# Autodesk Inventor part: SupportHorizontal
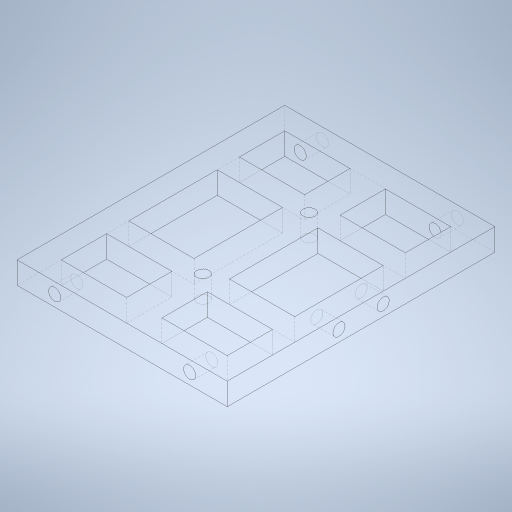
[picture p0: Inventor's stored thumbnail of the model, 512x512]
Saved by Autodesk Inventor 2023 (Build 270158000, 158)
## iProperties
Created: 2023-10
Part Number: SupportHorizontal
Material: Aluminum 7075
Document SubType Name: Modeling
Designer: tornqvih
Density: 2.81 g/cm^3
Appearance: Satin - Brushed Heavy
Author: tornqvih
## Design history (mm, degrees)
sketch "Sketch1"
  geometry: L1 (47.5, 60.5)-(-47.5, 60.5); L2 (-47.5, 60.5)-(-47.5, -60.5); L3 (-47.5, -60.5)-(47.5, -60.5); L4 (47.5, -60.5)-(47.5, 60.5); L5 (47.5, 60.5)-(-47.5, -60.5); L6 (-47.5, 60.5)-(47.5, -60.5); 1 further point
  constraints: 12 end point, 2 midpoint, 2 parallel, 1 horizontal, 1 perpendicular
  dimensions: "d0" = 121 distance of L3.end L1.start; "d1" = 95 distance of L1.start L1.end
extrude "Extrusion1" new body sketch "Sketch1" distance "d2" = 10; taper "d3" = 0 deg
sketch "Sketch2"
  geometry: L1 (-37.5, 50.5)-(-8, 50.5); L2 (-8, 50.5)-(-8, 30); L3 (-8, 30)-(-37.5, 30); L4 (-37.5, 30)-(-37.5, 50.5); L5 (8, 50.5)-(37.5, 50.5); L6 (37.5, 50.5)-(37.5, 30); L7 (37.5, 30)-(8, 30); L8 (8, 30)-(8, 50.5); L9 (-37.5, 20)-(-8, 20); L10 (-8, 20)-(-8, -20); L11 (-8, -20)-(-37.5, -20); L12 (-37.5, -20)-(-37.5, 20); L13 (8, 20)-(37.5, 20); L14 (37.5, 20)-(37.5, -20); L15 (37.5, -20)-(8, -20); L16 (8, -20)-(8, 20); L17 (-37.5, -30)-(-8, -30); L18 (-8, -30)-(-8, -50.5); L19 (-8, -50.5)-(-37.5, -50.5); L20 (-37.5, -50.5)-(-37.5, -30); L21 (8, -30)-(37.5, -30); L22 (37.5, -30)-(37.5, -50.5); L23 (37.5, -50.5)-(8, -50.5); L24 (8, -50.5)-(8, -30); L25 (0, 84.7)-(0, -84.7) reference; L26 (-66.5, 0)-(66.5, 0) reference; L27 (47.5, 60.5)-(-47.5, 60.5) reference; L28 (-47.5, 60.5)-(-47.5, -60.5) reference; 2 further points
  constraints: 48 end point, 18 symmetric about line, 12 parallel, 7 point on line, 6 horizontal, 6 perpendicular, 1 vertical alignment
  dimensions: "d4" = 10 distance between parallel lines of L27 L1; "d5" = 10 distance between parallel lines of L28 L4; "d8" = 20 distance between parallel lines of L26 L9; "d9" = 10 distance between parallel lines of L3 L9; "d43" = 16 distance between parallel lines of L8 L2
extrude "Extrusion2" cut sketch "Sketch2" distance "d10" = 10; taper "d11" = 0 deg
sketch "Sketch3"
  geometry: L1 (0, 10)-(95, 10) reference; L2 (0, 0)-(0, 10) reference; L3 (95, 0)-(95, 10) reference; 3 further points
  constraints: 1 horizontal alignment
  dimensions: "d12" = 5 distance from line of L1 point (17, 5); "d13" = 17 distance from line of L2 point (17, 5); "d14" = 17 distance from line of L3 point (78, 5)
hole "Hole1" sketch "Sketch3" at (17, 5), (78, 5) diameter "d15" = 5.5; stored, may be unused: countersink angle "d19" = 90 deg, drill point angle "d21" = 118 deg; dims "d16" = 6, "d17" = 4, "d18" = 2, "d20" = 10
sketch "Sketch4"
  geometry: L1 (0, 10)-(95, 10) reference; L2 (0, 0)-(0, 10) reference; L3 (95, 0)-(95, 10) reference; C1 r 2.75 at (78, 5) reference; C2 r 2.75 at (17, 5) reference; 3 further points
  constraints: 2 coincident
hole "Hole2" sketch "Sketch4" at (17, 5), (78, 5) diameter "d25" = 5.5; stored, may be unused: countersink angle "d29" = 90 deg, drill point angle "d31" = 118 deg; dims "d26" = 6, "d27" = 4, "d28" = 2, "d30" = 10
sketch "Sketch5"
  geometry: L1 (0, 10)-(121, 10) reference; L2 (0, 0)-(0, 10) reference; 5 further points
  constraints: 2 horizontal alignment, 1 midpoint
  dimensions: "d32" = 5 distance from line of L1 point (60.5, 5); "d33" = 10 distance of point (50.5, 5) point (60.5, 5); "d34" = 10 distance of point (70.5, 5) point (60.5, 5); "d53" = 60.5 distance from line of L2 point (60.5, 5)
hole "Hole3" sketch "Sketch5" at (50.5, 5), (70.5, 5) diameter "d35" = 5.5; stored, may be unused: countersink angle "d39" = 90 deg, drill point angle "d41" = 118 deg; dims "d36" = 6, "d37" = 4, "d38" = 2, "d40" = 10
sketch "Sketch6"
  geometry: L1 (-66.5, 0)-(66.5, 0) reference; L2 (0, 84.7)-(0, -84.7) reference; L3 (8, 20)-(37.5, 20) reference; 3 further points
  constraints: 1 point on line, 1 symmetric about line
  dimensions: "d45" = 4 distance from line of L3 point (0, 24)
hole "Hole4" sketch "Sketch6" at (0, 24), (0, -24) diameter "d46" = 5.5; stored, may be unused: countersink angle "d50" = 90 deg, drill point angle "d52" = 118 deg; dims "d47" = 6, "d48" = 4, "d49" = 2, "d51" = 10
body "Solid1"
